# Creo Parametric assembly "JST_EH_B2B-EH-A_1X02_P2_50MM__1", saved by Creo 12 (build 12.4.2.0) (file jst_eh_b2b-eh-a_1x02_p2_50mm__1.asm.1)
Units: Custom; MM, KILOGRAM, SECS

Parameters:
  PTC_WM_ITERATION = "0"
  PTC_WM_VERSION = "-.0"
  PTC_WM_LIFECYCLE_STATE = "In Work"
  PTC_WM_LIFECYCLE = "MO_CADDocument"
  PTC_WM_CREATED_BY = "Maximilian Roepper (Z0017RMS: MO)"
  PTC_WM_CREATED_ON = "18-Sep-26 11:36:42 AM"
  PTC_WM_MODIFIED_BY = "Maximilian Roepper (Z0017RMS: MO)"
  PTC_WM_MODIFIED_ON = "18-Sep-26 11:36:46 AM"
  PDMLINKNUMBER = "PDM000071454838"
  PTC_WM_NUMBER = "PDM000071454838"

Other parameters: WEIGHT, WEIGHT_FACTOR, WEIGHT_ADD, MC_ERRORS, SUPPLIER

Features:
  1. coordinate system
  2. imported feature
  3. component "JST_B2B_EH_A_1"

Other named items: DRW_VIEW_ORG, ROUGH-GROB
